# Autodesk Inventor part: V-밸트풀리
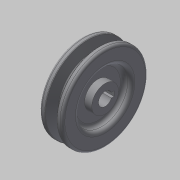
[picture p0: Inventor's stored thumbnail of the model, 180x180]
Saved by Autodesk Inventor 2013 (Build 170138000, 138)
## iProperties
Created: 2015-02
Part Number: V-밸트풀리
Material: 일반
Document SubType Name: Modeling
Designer: Administrator
Density: 1 g/cm^3
Author: Administrator
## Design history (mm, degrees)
sketch "스케치1"
  geometry: L1 (0, 0)-(25, 0); L2 (0, 5.5)-(0, 11); L3 (0, 11)-(6, 11); L4 (6, 11)-(6, 21.5); L5 (6, 21.5)-(0, 21.5); L6 (0, 21.5)-(0, 35.2); L7 (0, 35.2)-(4.675, 35.2); L8 (4.675, 35.2)-(7.426, 26.2); L9 (7.426, 26.2)-(11.574, 26.2); L10 (11.574, 26.2)-(14.325, 35.2); L11 (14.325, 35.2)-(19, 35.2); L12 (19, 35.2)-(19, 21.5); L13 (19, 21.5)-(13, 21.5); L14 (13, 21.5)-(13, 11); L15 (13, 11)-(25, 11); L16 (25, 11)-(25, 5.5); L17 (5.5, 32.5)-(13.5, 32.5); L18 (0, 5.5)-(25, 5.5); 6 further points
  constraints: 36 end point, 9 parallel, 5 midpoint, 4 equal length, 4 perpendicular, 4 vertical alignment, 3 collinear, 2 coincident, 2 point on line, 1 horizontal
  dimensions: "d0" = 25 distance of L1.start L1.end; "d1" = 6 distance of L4.end L5.end; "d2" = 34 deg angle of L10 L8; "d3" = 65 diameter of L17 L1; "d4" = 8 distance of L17.start L17.end; "d5" = 43 diameter of L5 L1; "d6" = 22 diameter of L15 L1; "d7" = 19 distance between parallel lines of L6 L12; "d8" = 6.3 distance between parallel lines of L9 L17; "d9" = 2.7 distance between parallel lines of L17 L11; "d10" = 11 diameter of L18 L1
revolve "회전1" sketch "스케치1" stored, may be unused: angle "d11" = 90 deg
sketch "스케치2"
  geometry: L1 (-2, 5.123)-(-2, 7.3); L2 (-2, 7.3)-(2, 7.3); L3 (2, 7.3)-(2, 5.123); A1 r 5.5 centre (0, 0) between (-2, 5.123) and (2, 5.123) reference; 1 further point
  constraints: 6 end point, 2 point on circle, 1 midpoint, 1 parallel, 1 perpendicular, 1 vertical, 1 vertical alignment
  dimensions: "d12" = 4 distance of L1.end L2.end; "d14" = 7.3 distance from line of L2 A1.centre
extrude "돌출1" cut sketch "스케치2" distance "d15" = 34.5; taper "d16" = 0 deg
fillet "모깎기1" dims "d17" = 1
fillet "모깎기2" dims "d18" = 0.5
fillet "모깎기3" dims "d19" = 2
fillet "모깎기4" dims "d20" = 3
node "솔리드1"
